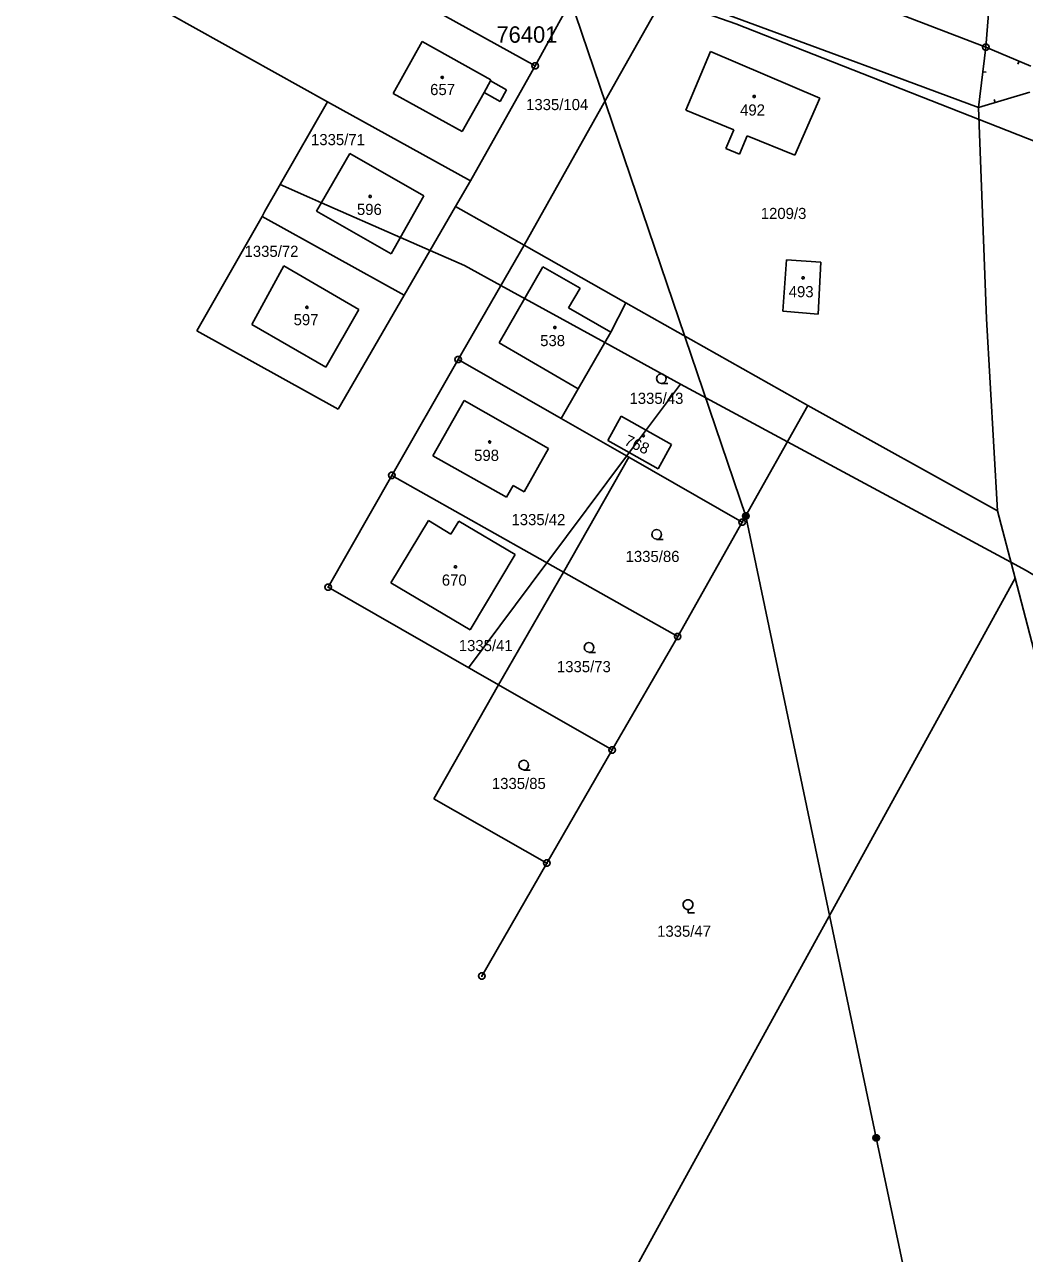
# Model space of a CAD drawing. Extents: x -789470 to -786707, y -1118640 to -1114455.
# Drawn here: x -787858.4 to -787706, y -1116838.5 to -1116651.3 of the extents above; entities that cross this region are included whole.
import ezdxf

# ---------------------------------------------------------------- set-up
doc = ezdxf.new("R2010")
doc.units = 0
for name, color, linetype in [('1', 7, 'Continuous'), ('11', 7, 'Continuous'), ('12', 7, 'Continuous'), ('13', 7, 'Continuous'), ('2', 7, 'Continuous'), ('3', 7, 'Continuous'), ('4', 7, 'Continuous'), ('5', 7, 'Continuous'), ('6', 7, 'Continuous'), ('8', 7, 'Continuous')]:
    doc.layers.add(name, color=color, linetype=linetype)

msp = doc.modelspace()

# ---------------------------------------------------------------- linework, layer by layer
at = {"layer": '1'}
for p, q in [((-787709.96, -1116629.67), (-787711.9, -1116654.76)), ((-787711.9, -1116654.76), (-787758.02, -1116637.02)), ((-787780.6, -1116657.6), (-787772.01, -1116642.03)), ((-787768.23, -1116659.94), (-787760.59, -1116646.36)), ((-787734.55, -1116655.99), (-787760.59, -1116646.36)), ((-787796.51, -1116648.8), (-787780.6, -1116657.6)), ((-787836.33, -1116649.69), (-787812.26, -1116663.09)), ((-787802.22, -1116661.79), (-787797.83, -1116653.91)), ((-787797.83, -1116653.91), (-787787.33, -1116659.73)), ((-787711.9, -1116654.76), (-787713, -1116663.97)), ((-787757.64, -1116664.34), (-787753.87, -1116655.44)), ((-787753.87, -1116655.44), (-787737.21, -1116662.52)), ((-787727.41, -1116658.64), (-787734.55, -1116655.99)), ((-787790.46, -1116675.1), (-787780.6, -1116657.6)), ((-787713, -1116663.97), (-787727.41, -1116658.64)), ((-787787.33, -1116659.73), (-787787.42, -1116659.89)), ((-787787.42, -1116659.89), (-787784.95, -1116661.27)), ((-787782.28, -1116684.92), (-787768.23, -1116659.94)), ((-787791.72, -1116667.61), (-787802.22, -1116661.79)), ((-787788.39, -1116661.64), (-787791.72, -1116667.61)), ((-787785.93, -1116663.01), (-787788.39, -1116661.64)), ((-787784.95, -1116661.27), (-787785.93, -1116663.01)), ((-787737.21, -1116662.52), (-787741.02, -1116671.19)), ((-787821.78, -1116679.76), (-787812.26, -1116663.09)), ((-787812.26, -1116663.09), (-787790.46, -1116675.1)), ((-787750.32, -1116667.37), (-787757.64, -1116664.34)), ((-787713, -1116663.97), (-787711.8, -1116696.13)), ((-787751.52, -1116670.22), (-787750.32, -1116667.37)), ((-787748.26, -1116668.24), (-787749.46, -1116671.08)), ((-787741.02, -1116671.19), (-787748.26, -1116668.24)), ((-787808.86, -1116670.96), (-787813.91, -1116679.76)), ((-787797.54, -1116677.42), (-787808.86, -1116670.96)), ((-787749.46, -1116671.08), (-787751.52, -1116670.22)), ((-787790.46, -1116675.1), (-787792.73, -1116679.02)), ((-787802.56, -1116686.23), (-787797.54, -1116677.42)), ((-787792.73, -1116679.02), (-787800.54, -1116692.52)), ((-787782.28, -1116684.92), (-787792.73, -1116679.02)), ((-787832.17, -1116698), (-787822.22, -1116680.54)), ((-787822.22, -1116680.54), (-787821.78, -1116679.76)), ((-787822.22, -1116680.54), (-787800.54, -1116692.52)), ((-787813.91, -1116679.76), (-787802.56, -1116686.23)), ((-787792.32, -1116702.35), (-787782.28, -1116684.92)), ((-787766.76, -1116693.69), (-787782.28, -1116684.92)), ((-787818.9, -1116688.06), (-787823.8, -1116697)), ((-787807.45, -1116694.71), (-787818.9, -1116688.06)), ((-787742.85, -1116694.96), (-787742.29, -1116687.14)), ((-787742.29, -1116687.14), (-787737.04, -1116687.53)), ((-787737.04, -1116687.53), (-787737.48, -1116695.46)), ((-787810.61, -1116709.92), (-787800.54, -1116692.52)), ((-787766.76, -1116693.69), (-787769.07, -1116698.19)), ((-787739.04, -1116709.34), (-787766.76, -1116693.69)), ((-787812.51, -1116703.51), (-787807.45, -1116694.71)), ((-787737.48, -1116695.46), (-787742.85, -1116694.96)), ((-787711.8, -1116696.13), (-787710.11, -1116725.38)), ((-787832.17, -1116698), (-787810.61, -1116709.92)), ((-787823.8, -1116697), (-787812.51, -1116703.51)), ((-787769.07, -1116698.19), (-787774.02, -1116706.81)), ((-787802.43, -1116720), (-787792.32, -1116702.35)), ((-787776.64, -1116711.32), (-787792.32, -1116702.35)), ((-787774.02, -1116706.81), (-787776.64, -1116711.32)), ((-787796.18, -1116717), (-787791.43, -1116708.59)), ((-787791.43, -1116708.59), (-787778.54, -1116715.88)), ((-787769.54, -1116714.67), (-787767.47, -1116710.96)), ((-787767.47, -1116710.96), (-787759.8, -1116715.3)), ((-787739.04, -1116709.34), (-787749.02, -1116727.15)), ((-787710.11, -1116725.38), (-787739.04, -1116709.34)), ((-787766.34, -1116717.23), (-787776.64, -1116711.32)), ((-787761.87, -1116718.98), (-787769.54, -1116714.67)), ((-787778.54, -1116715.88), (-787782.28, -1116722.5)), ((-787759.8, -1116715.3), (-787761.87, -1116718.98)), ((-787784.94, -1116723.32), (-787796.18, -1116717)), ((-787766.34, -1116717.23), (-787776.27, -1116734.75)), ((-787749.02, -1116727.15), (-787766.34, -1116717.23)), ((-787812.15, -1116737.05), (-787802.43, -1116720)), ((-787776.27, -1116734.75), (-787802.43, -1116720)), ((-787783.94, -1116721.56), (-787784.94, -1116723.32)), ((-787782.28, -1116722.5), (-787783.94, -1116721.56)), ((-787710.11, -1116725.38), (-787707.44, -1116735.64)), ((-787802.59, -1116736.35), (-787796.87, -1116726.88)), ((-787796.87, -1116726.88), (-787793.43, -1116728.94)), ((-787793.43, -1116728.94), (-787792.24, -1116726.96)), ((-787792.24, -1116726.96), (-787783.66, -1116732.08)), ((-787749.02, -1116727.15), (-787758.87, -1116744.56)), ((-787783.66, -1116732.08), (-787790.5, -1116743.52)), ((-787786.17, -1116751.92), (-787776.27, -1116734.75)), ((-787758.87, -1116744.56), (-787776.27, -1116734.75)), ((-787707.44, -1116735.64), (-787858.42, -1117009.87)), ((-787786.17, -1116751.92), (-787812.15, -1116737.05)), ((-787790.5, -1116743.52), (-787802.59, -1116736.35)), ((-787707.44, -1116735.64), (-787699.48, -1116766.3)), ((-787758.87, -1116744.56), (-787768.85, -1116761.84)), ((-787786.17, -1116751.92), (-787796.05, -1116769.26)), ((-787768.85, -1116761.84), (-787786.17, -1116751.92)), ((-787768.85, -1116761.84), (-787778.8, -1116779.08)), ((-787778.8, -1116779.08), (-787796.05, -1116769.26)), ((-787778.8, -1116779.08), (-787788.72, -1116796.28))]:
    msp.add_line(p, q, dxfattribs=at)
at = {"layer": '11'}
for points in [[(-787693.43, -1116671.58), (-787694.19, -1116671.43), (-787702.73, -1116669.8), (-787712.93, -1116665.78), (-787750.01, -1116651.19), (-787761.1, -1116647.27), (-787763.53, -1116646.41), (-787769.34, -1116643.04), (-787790.93, -1116630.52), (-787799.79, -1116626.21), (-787809.71, -1116621.47)], [(-787758.46, -1116706.09), (-787769.97, -1116699.76), (-787785.82, -1116691.06), (-787791.35, -1116688.03), (-787796.61, -1116685.72), (-787801.14, -1116683.74), (-787813.17, -1116678.46), (-787814.99, -1116677.66), (-787819.46, -1116675.69)], [(-787790.75, -1116749.3), (-787778.81, -1116733.32), (-787766.65, -1116717.05), (-787758.46, -1116706.09)], [(-787758.46, -1116706.09), (-787742.14, -1116714.87), (-787708.07, -1116733.22), (-787705.74, -1116734.47), (-787690.47, -1116743.7), (-787656, -1116764.52), (-787635.75, -1116774.85), (-787632.38, -1116777.42), (-787599.9, -1116794.21), (-787581.34, -1116802.84), (-787573.75, -1116807.56)]]:
    msp.add_lwpolyline(points, dxfattribs=at)
at = {"layer": '12'}
for p, q in [((-787802.22, -1116661.79), (-787797.83, -1116653.91)), ((-787797.83, -1116653.91), (-787787.33, -1116659.73)), ((-787757.64, -1116664.34), (-787753.87, -1116655.44)), ((-787753.87, -1116655.44), (-787737.21, -1116662.52)), ((-787788.39, -1116661.64), (-787787.42, -1116659.89)), ((-787787.33, -1116659.73), (-787787.42, -1116659.89)), ((-787791.72, -1116667.61), (-787802.22, -1116661.79)), ((-787788.39, -1116661.64), (-787791.72, -1116667.61)), ((-787737.21, -1116662.52), (-787741.02, -1116671.19)), ((-787750.32, -1116667.37), (-787757.64, -1116664.34)), ((-787751.52, -1116670.22), (-787750.32, -1116667.37)), ((-787748.26, -1116668.24), (-787749.46, -1116671.08)), ((-787741.02, -1116671.19), (-787748.26, -1116668.24)), ((-787808.86, -1116670.96), (-787813.91, -1116679.76)), ((-787797.54, -1116677.42), (-787808.86, -1116670.96)), ((-787749.46, -1116671.08), (-787751.52, -1116670.22)), ((-787802.56, -1116686.23), (-787797.54, -1116677.42)), ((-787813.91, -1116679.76), (-787802.56, -1116686.23)), ((-787818.9, -1116688.06), (-787823.8, -1116697)), ((-787807.45, -1116694.71), (-787818.9, -1116688.06)), ((-787786.1, -1116699.83), (-787779.42, -1116688.21)), ((-787779.42, -1116688.21), (-787773.76, -1116691.48)), ((-787742.85, -1116694.96), (-787742.29, -1116687.14)), ((-787742.29, -1116687.14), (-787737.04, -1116687.53)), ((-787737.04, -1116687.53), (-787737.48, -1116695.46)), ((-787773.76, -1116691.48), (-787775.49, -1116694.49)), ((-787812.51, -1116703.51), (-787807.45, -1116694.71)), ((-787775.49, -1116694.49), (-787769.07, -1116698.19)), ((-787737.48, -1116695.46), (-787742.85, -1116694.96)), ((-787823.8, -1116697), (-787812.51, -1116703.51)), ((-787774.02, -1116706.81), (-787786.1, -1116699.83)), ((-787769.07, -1116698.19), (-787774.02, -1116706.81)), ((-787796.18, -1116717), (-787791.43, -1116708.59)), ((-787791.43, -1116708.59), (-787778.54, -1116715.88)), ((-787769.54, -1116714.67), (-787767.47, -1116710.96)), ((-787767.47, -1116710.96), (-787759.8, -1116715.3)), ((-787761.87, -1116718.98), (-787769.54, -1116714.67)), ((-787778.54, -1116715.88), (-787782.28, -1116722.5)), ((-787759.8, -1116715.3), (-787761.87, -1116718.98)), ((-787784.94, -1116723.32), (-787796.18, -1116717)), ((-787783.94, -1116721.56), (-787784.94, -1116723.32)), ((-787782.28, -1116722.5), (-787783.94, -1116721.56)), ((-787802.59, -1116736.35), (-787796.87, -1116726.88)), ((-787796.87, -1116726.88), (-787793.43, -1116728.94)), ((-787793.43, -1116728.94), (-787792.24, -1116726.96)), ((-787792.24, -1116726.96), (-787783.66, -1116732.08)), ((-787783.66, -1116732.08), (-787790.5, -1116743.52)), ((-787790.5, -1116743.52), (-787802.59, -1116736.35))]:
    msp.add_line(p, q, dxfattribs=at)
at = {"layer": '13'}
for p, q in [((-787713, -1116663.97), (-787711.9, -1116654.76)), ((-787711.9, -1116654.76), (-787705.05, -1116657.63)), ((-787706.83, -1116656.89), (-787707.02, -1116657.35)), ((-787712.35, -1116658.51), (-787711.85, -1116658.57)), ((-787705.21, -1116661.61), (-787713, -1116663.97)), ((-787710.47, -1116663.2), (-787710.62, -1116662.73))]:
    msp.add_line(p, q, dxfattribs=at)
at = {"layer": '3'}
for points in [[(-787761.36, -1116705.99), (-787761.74, -1116705.89), (-787762.01, -1116705.62), (-787762.11, -1116705.25), (-787762.01, -1116704.88), (-787761.74, -1116704.61), (-787761.37, -1116704.51), (-787761, -1116704.61), (-787760.73, -1116704.88), (-787760.63, -1116705.26), (-787760.73, -1116705.64), (-787761, -1116705.91), (-787761.38, -1116706.01), (-787760.38, -1116706.01)], [(-787762.07, -1116729.73), (-787762.45, -1116729.63), (-787762.72, -1116729.36), (-787762.82, -1116728.99), (-787762.72, -1116728.62), (-787762.45, -1116728.35), (-787762.08, -1116728.25), (-787761.71, -1116728.35), (-787761.44, -1116728.62), (-787761.34, -1116729), (-787761.44, -1116729.38), (-787761.71, -1116729.65), (-787762.09, -1116729.75), (-787761.09, -1116729.75)], [(-787772.38, -1116746.96), (-787772.76, -1116746.86), (-787773.03, -1116746.59), (-787773.13, -1116746.22), (-787773.03, -1116745.85), (-787772.76, -1116745.58), (-787772.39, -1116745.48), (-787772.02, -1116745.58), (-787771.75, -1116745.85), (-787771.65, -1116746.23), (-787771.75, -1116746.61), (-787772.02, -1116746.88), (-787772.4, -1116746.98), (-787771.4, -1116746.98)], [(-787782.32, -1116764.88), (-787782.7, -1116764.78), (-787782.97, -1116764.51), (-787783.07, -1116764.14), (-787782.97, -1116763.77), (-787782.7, -1116763.5), (-787782.33, -1116763.4), (-787781.96, -1116763.5), (-787781.69, -1116763.77), (-787781.59, -1116764.15), (-787781.69, -1116764.53), (-787781.96, -1116764.8), (-787782.34, -1116764.9), (-787781.34, -1116764.9)], [(-787757.3, -1116786.12), (-787757.49, -1116786.12), (-787757.83, -1116785.93), (-787758.02, -1116785.59), (-787758.02, -1116785.2), (-787757.83, -1116784.86), (-787757.49, -1116784.67), (-787757.1, -1116784.67), (-787756.76, -1116784.86), (-787756.57, -1116785.2), (-787756.57, -1116785.59), (-787756.76, -1116785.93), (-787757.1, -1116786.12), (-787757.29, -1116786.12), (-787757.29, -1116786.65), (-787756.29, -1116786.65)]]:
    msp.add_lwpolyline(points, dxfattribs=at)
at = {"layer": '4'}
for p, q in [((-787788.39, -1116661.64), (-787787.42, -1116659.89)), ((-787786.1, -1116699.83), (-787779.42, -1116688.21)), ((-787779.42, -1116688.21), (-787773.76, -1116691.48)), ((-787773.76, -1116691.48), (-787775.49, -1116694.49)), ((-787775.49, -1116694.49), (-787769.07, -1116698.19)), ((-787774.02, -1116706.81), (-787786.1, -1116699.83))]:
    msp.add_line(p, q, dxfattribs=at)
at = {"layer": '5'}
for points in [[(-787794.75, -1116659.19), (-787794.65, -1116659.21), (-787794.6, -1116659.3), (-787794.58, -1116659.36), (-787794.6, -1116659.45), (-787794.68, -1116659.52), (-787794.75, -1116659.53), (-787794.84, -1116659.5), (-787794.9, -1116659.44), (-787794.92, -1116659.36), (-787794.9, -1116659.27), (-787794.82, -1116659.2)], [(-787747.21, -1116662.09), (-787747.11, -1116662.11), (-787747.06, -1116662.2), (-787747.04, -1116662.26), (-787747.06, -1116662.35), (-787747.14, -1116662.42), (-787747.21, -1116662.43), (-787747.3, -1116662.4), (-787747.36, -1116662.34), (-787747.38, -1116662.26), (-787747.36, -1116662.17), (-787747.28, -1116662.1)], [(-787805.76, -1116677.33), (-787805.66, -1116677.35), (-787805.61, -1116677.44), (-787805.59, -1116677.5), (-787805.61, -1116677.59), (-787805.69, -1116677.66), (-787805.76, -1116677.67), (-787805.85, -1116677.64), (-787805.91, -1116677.58), (-787805.93, -1116677.5), (-787805.91, -1116677.41), (-787805.83, -1116677.34)], [(-787739.76, -1116689.74), (-787739.66, -1116689.76), (-787739.61, -1116689.85), (-787739.59, -1116689.91), (-787739.61, -1116690), (-787739.69, -1116690.07), (-787739.76, -1116690.08), (-787739.85, -1116690.05), (-787739.91, -1116689.99), (-787739.93, -1116689.91), (-787739.91, -1116689.82), (-787739.83, -1116689.75)], [(-787815.38, -1116694.23), (-787815.28, -1116694.25), (-787815.23, -1116694.34), (-787815.21, -1116694.4), (-787815.23, -1116694.49), (-787815.31, -1116694.56), (-787815.38, -1116694.57), (-787815.47, -1116694.54), (-787815.53, -1116694.48), (-787815.55, -1116694.4), (-787815.53, -1116694.31), (-787815.45, -1116694.24)], [(-787777.59, -1116697.3), (-787777.49, -1116697.32), (-787777.44, -1116697.41), (-787777.42, -1116697.47), (-787777.44, -1116697.56), (-787777.52, -1116697.63), (-787777.59, -1116697.64), (-787777.68, -1116697.61), (-787777.74, -1116697.55), (-787777.76, -1116697.47), (-787777.74, -1116697.38), (-787777.66, -1116697.31)], [(-787787.53, -1116714.75), (-787787.43, -1116714.77), (-787787.38, -1116714.86), (-787787.36, -1116714.92), (-787787.38, -1116715.01), (-787787.46, -1116715.08), (-787787.53, -1116715.09), (-787787.62, -1116715.06), (-787787.68, -1116715), (-787787.7, -1116714.92), (-787787.68, -1116714.83), (-787787.6, -1116714.76)], [(-787764.11, -1116713.78), (-787764.01, -1116713.8), (-787763.96, -1116713.89), (-787763.94, -1116713.95), (-787763.96, -1116714.04), (-787764.04, -1116714.11), (-787764.11, -1116714.12), (-787764.2, -1116714.09), (-787764.26, -1116714.03), (-787764.28, -1116713.95), (-787764.26, -1116713.86), (-787764.18, -1116713.79)], [(-787792.76, -1116733.77), (-787792.66, -1116733.79), (-787792.61, -1116733.88), (-787792.59, -1116733.94), (-787792.61, -1116734.03), (-787792.69, -1116734.1), (-787792.76, -1116734.11), (-787792.85, -1116734.08), (-787792.91, -1116734.02), (-787792.93, -1116733.94), (-787792.91, -1116733.85), (-787792.83, -1116733.78)]]:
    msp.add_lwpolyline(points, close=True, dxfattribs=at)
at = {"layer": '6'}
for p, q in [((-787782.31, -1116626.62), (-787748.48, -1116726.19)), ((-787748.48, -1116726.19), (-787728.61, -1116820.94)), ((-787706.26, -1116926.46), (-787728.61, -1116820.94))]:
    msp.add_line(p, q, dxfattribs=at)
for points in [[(-787748.63, -1116725.71), (-787748.32, -1116725.71), (-787748.07, -1116725.89), (-787747.97, -1116726.18), (-787748.07, -1116726.47), (-787748.32, -1116726.65), (-787748.63, -1116726.65), (-787748.88, -1116726.47), (-787748.98, -1116726.18), (-787748.88, -1116725.89), (-787748.63, -1116725.71), (-787748.6, -1116725.75), (-787748.36, -1116725.75), (-787748.2, -1116725.83), (-787748.76, -1116725.83), (-787748.84, -1116725.91), (-787748.12, -1116725.91), (-787748.12, -1116725.99), (-787748.84, -1116725.99), (-787748.88, -1116726.07), (-787748.08, -1116726.07), (-787748.04, -1116726.15), (-787748.92, -1116726.15), (-787748.92, -1116726.23), (-787748.04, -1116726.23), (-787748.07, -1116726.31), (-787748.88, -1116726.31), (-787748.87, -1116726.39), (-787748.06, -1116726.39), (-787748.11, -1116726.47), (-787748.83, -1116726.47), (-787748.75, -1116726.55), (-787748.19, -1116726.55), (-787748.3, -1116726.63), (-787748.64, -1116726.63)], [(-787728.76, -1116820.46), (-787728.45, -1116820.46), (-787728.2, -1116820.64), (-787728.1, -1116820.93), (-787728.2, -1116821.22), (-787728.45, -1116821.4), (-787728.76, -1116821.4), (-787729.01, -1116821.22), (-787729.11, -1116820.93), (-787729.01, -1116820.64), (-787728.76, -1116820.46), (-787728.73, -1116820.5), (-787728.49, -1116820.5), (-787728.33, -1116820.58), (-787728.89, -1116820.58), (-787728.97, -1116820.66), (-787728.25, -1116820.66), (-787728.25, -1116820.74), (-787728.97, -1116820.74), (-787729.01, -1116820.82), (-787728.21, -1116820.82), (-787728.17, -1116820.9), (-787729.05, -1116820.9), (-787729.05, -1116820.98), (-787728.17, -1116820.98), (-787728.2, -1116821.06), (-787729.01, -1116821.06), (-787729, -1116821.14), (-787728.19, -1116821.14), (-787728.24, -1116821.22), (-787728.96, -1116821.22), (-787728.88, -1116821.3), (-787728.32, -1116821.3), (-787728.43, -1116821.38), (-787728.77, -1116821.38)]]:
    msp.add_lwpolyline(points, dxfattribs=at)
at = {"layer": '8'}
for p, q in [((-787712.02, -1116654.76), (-787711.78, -1116654.76)), ((-787780.72, -1116657.6), (-787780.48, -1116657.6)), ((-787792.44, -1116702.35), (-787792.2, -1116702.35)), ((-787802.55, -1116720), (-787802.31, -1116720)), ((-787749.14, -1116727.15), (-787748.9, -1116727.15)), ((-787812.27, -1116737.05), (-787812.03, -1116737.05)), ((-787758.99, -1116744.56), (-787758.75, -1116744.56)), ((-787768.97, -1116761.84), (-787768.73, -1116761.84)), ((-787778.92, -1116779.08), (-787778.68, -1116779.08)), ((-787788.84, -1116796.28), (-787788.6, -1116796.28))]:
    msp.add_line(p, q, dxfattribs=at)
for points in [[(-787711.75, -1116654.28), (-787711.5, -1116654.46), (-787711.4, -1116654.75), (-787711.5, -1116655.04), (-787711.75, -1116655.22), (-787712.06, -1116655.22), (-787712.31, -1116655.04), (-787712.41, -1116654.75), (-787712.31, -1116654.46), (-787712.06, -1116654.28)], [(-787780.45, -1116657.12), (-787780.2, -1116657.3), (-787780.1, -1116657.59), (-787780.2, -1116657.88), (-787780.45, -1116658.06), (-787780.76, -1116658.06), (-787781.01, -1116657.88), (-787781.11, -1116657.59), (-787781.01, -1116657.3), (-787780.76, -1116657.12)], [(-787792.17, -1116701.87), (-787791.92, -1116702.05), (-787791.82, -1116702.34), (-787791.92, -1116702.63), (-787792.17, -1116702.81), (-787792.48, -1116702.81), (-787792.73, -1116702.63), (-787792.83, -1116702.34), (-787792.73, -1116702.05), (-787792.48, -1116701.87)], [(-787802.28, -1116719.52), (-787802.03, -1116719.7), (-787801.93, -1116719.99), (-787802.03, -1116720.28), (-787802.28, -1116720.46), (-787802.59, -1116720.46), (-787802.84, -1116720.28), (-787802.94, -1116719.99), (-787802.84, -1116719.7), (-787802.59, -1116719.52)], [(-787748.87, -1116726.67), (-787748.62, -1116726.85), (-787748.52, -1116727.14), (-787748.62, -1116727.43), (-787748.87, -1116727.61), (-787749.18, -1116727.61), (-787749.43, -1116727.43), (-787749.53, -1116727.14), (-787749.43, -1116726.85), (-787749.18, -1116726.67)], [(-787812, -1116736.57), (-787811.75, -1116736.75), (-787811.65, -1116737.04), (-787811.75, -1116737.33), (-787812, -1116737.51), (-787812.31, -1116737.51), (-787812.56, -1116737.33), (-787812.66, -1116737.04), (-787812.56, -1116736.75), (-787812.31, -1116736.57)], [(-787758.72, -1116744.08), (-787758.47, -1116744.26), (-787758.37, -1116744.55), (-787758.47, -1116744.84), (-787758.72, -1116745.02), (-787759.03, -1116745.02), (-787759.28, -1116744.84), (-787759.38, -1116744.55), (-787759.28, -1116744.26), (-787759.03, -1116744.08)], [(-787768.7, -1116761.36), (-787768.45, -1116761.54), (-787768.35, -1116761.83), (-787768.45, -1116762.12), (-787768.7, -1116762.3), (-787769.01, -1116762.3), (-787769.26, -1116762.12), (-787769.36, -1116761.83), (-787769.26, -1116761.54), (-787769.01, -1116761.36)], [(-787778.65, -1116778.6), (-787778.4, -1116778.78), (-787778.3, -1116779.07), (-787778.4, -1116779.36), (-787778.65, -1116779.54), (-787778.96, -1116779.54), (-787779.21, -1116779.36), (-787779.31, -1116779.07), (-787779.21, -1116778.78), (-787778.96, -1116778.6)], [(-787788.57, -1116795.8), (-787788.32, -1116795.98), (-787788.22, -1116796.27), (-787788.32, -1116796.56), (-787788.57, -1116796.74), (-787788.88, -1116796.74), (-787789.13, -1116796.56), (-787789.23, -1116796.27), (-787789.13, -1116795.98), (-787788.88, -1116795.8)]]:
    msp.add_lwpolyline(points, close=True, dxfattribs=at)

# ---------------------------------------------------------------- texts
at = {"layer": '11'}
msp.add_text('76401', height=2.5, dxfattribs=at).set_placement((-787786.5, -1116654.08))
at = {"layer": '2'}
for s, p in [('657', (-787796.6, -1116662.06)), ('1335/104', (-787781.98, -1116664.35)), ('492', (-787749.36, -1116665.18)), ('1335/71', (-787814.76, -1116669.69)), ('596', (-787807.76, -1116680.32)), ('1209/3', (-787746.21, -1116680.94)), ('1335/72', (-787824.89, -1116686.71)), ('493', (-787741.95, -1116692.86)), ('597', (-787817.41, -1116697.12)), ('538', (-787779.83, -1116700.31)), ('1335/43', (-787766.22, -1116709.11)), ('598', (-787789.9, -1116717.8)), ('1335/42', (-787784.21, -1116727.59)), ('1335/86', (-787766.81, -1116733.2)), ('670', (-787794.82, -1116736.8)), ('1335/41', (-787792.24, -1116746.78)), ('1335/73', (-787777.28, -1116749.99)), ('1335/85', (-787787.19, -1116767.79)), ('1335/47', (-787762.01, -1116790.3))]:
    msp.add_text(s, height=1.7, dxfattribs=at).set_placement(p)
msp.add_text('768', height=1.7, rotation=335.7533, dxfattribs=at).set_placement((-787767.14, -1116715.29))

doc.saveas('drawing.dxf')
